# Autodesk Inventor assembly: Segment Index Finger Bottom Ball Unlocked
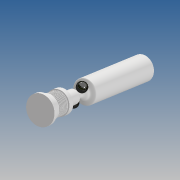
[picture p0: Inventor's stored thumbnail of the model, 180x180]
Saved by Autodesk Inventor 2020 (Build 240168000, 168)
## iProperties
Created: 2019-10
Part Number: Segment Index Finger Bottom Ball Unlocked
Document SubType Name: Assembly
Designer: yello
Author: yello
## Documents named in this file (6)
- C:\Users\yello\Documents\Mechanical Hand\Prototype 2 (Realistic Hand)\Segment Index Finger Bottom Ball Unlocked.iam
- C:\Users\yello\Documents\Mechanical Hand\Prototype 2 (Realistic Hand)\Segment Index Finger Bottom.ipt
- C:\Users\yello\Documents\Mechanical Hand\Prototype 2 (Realistic Hand)\Push Part.ipt
- C:\Users\yello\Documents\Mechanical Hand\Prototype 2 (Realistic Hand)\Plug.ipt
- C:\Users\yello\Documents\Mechanical Hand\Prototype 2 (Realistic Hand)\Ball.ipt
- C:\Users\yello\Documents\Mechanical Hand\Prototype 2 (Realistic Hand)\Spring 2.ipt
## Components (6 placed, 5 different names)
1. Segment Index Finger Bottom:1 — Mate:1, Mate:2, Mate:3, Mate:6, Mate:7
2. Push Part:1 — Mate:1, Mate:8
3. Plug:1 — Mate:2, Mate:3
4. Ball:1 — Mate:6
5. Ball:2 — Mate:7
6. Spring 2:1 — Mate:8
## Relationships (6: Mate 6)
- Mate:1: Segment Index Finger Bottom:1 ↔ Push Part:1
- Mate:2: Segment Index Finger Bottom:1 ↔ Plug:1
- Mate:3: Segment Index Finger Bottom:1 ↔ Plug:1
- Mate:6: Segment Index Finger Bottom:1 ↔ Ball:1
- Mate:7: Segment Index Finger Bottom:1 ↔ Ball:2
- Mate:8: Push Part:1 ↔ Spring 2:1
